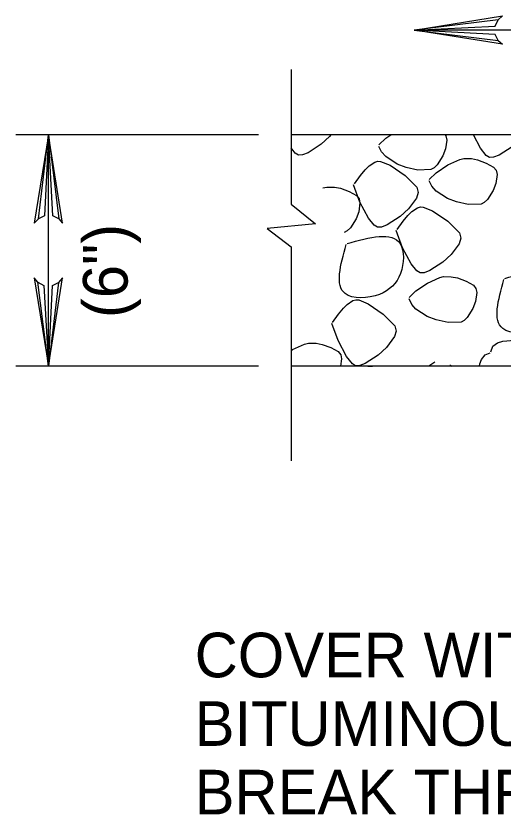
# Model space of a CAD drawing. Extents: x 638455 to 640199, y 298558 to 299152.
# Drawn here: x 639393.4 to 639430.1, y 298625.3 to 298685.5 of the extents above; entities that cross this region are included whole.
import ezdxf

# ---------------------------------------------------------------- set-up
doc = ezdxf.new("R2010")
doc.units = 0
doc.layers.add('2', color=7, linetype='Continuous')
doc.layers.add('3', color=7, linetype='Continuous')

msp = doc.modelspace()

# ---------------------------------------------------------------- linework, layer by layer
at = {"layer": '2'}
for p, q in [((639414.143, 298681.461), (639414.143, 298671.317)), ((639411.704, 298676.533), (639393.444, 298676.533)), ((639395.883, 298659.109), (639395.883, 298676.533)), ((639454.982, 298676.533), (639414.143, 298676.533)), ((639414.143, 298668.094), (639414.143, 298651.994)), ((639411.704, 298659.109), (639393.444, 298659.109)), ((639522.815, 298659.109), (639414.143, 298659.109))]:
    msp.add_line(p, q, dxfattribs=at)
for points in [[(639429.74, 298683.637), (639429.502, 298684.093), (639423.409, 298684.43), (639429.74, 298683.637), (639430.063, 298683.359), (639423.409, 298684.43), (639429.499, 298684.732), (639429.72, 298685.185), (639423.409, 298684.43), (639430.063, 298685.487), (639429.72, 298685.185)], [(639447.803, 298684.43), (639430.379, 298684.43), (639423.409, 298684.43)], [(639396.676, 298670.205), (639396.217, 298670.44), (639395.883, 298676.533), (639396.676, 298670.205), (639396.955, 298669.88), (639395.883, 298676.533), (639395.581, 298670.446), (639395.128, 298670.222), (639395.883, 298676.533), (639394.823, 298669.88), (639395.128, 298670.222)], [(639417.039, 298676.405), (639416.411, 298675.827)], [(639417.134, 298676.533), (639417.039, 298676.405)], [(639421.284, 298676.28), (639421.665, 298676.533)], [(639425.739, 298676.533), (639425.797, 298676.46)], [(639425.797, 298676.46), (639425.858, 298676.146)], [(639428.39, 298675.522), (639427.865, 298676.533)], [(639416.411, 298675.827), (639415.433, 298675.182)], [(639420.759, 298675.778), (639421.284, 298676.28)], [(639425.858, 298676.146), (639425.759, 298675.478)], [(639414.463, 298675.165), (639414.143, 298675.551)], [(639414.71, 298675.017), (639414.463, 298675.165)], [(639415.433, 298675.182), (639415.018, 298675.025)], [(639420.962, 298675.255), (639420.759, 298675.664)], [(639421.276, 298674.895), (639420.962, 298675.255)], [(639425.759, 298675.478), (639425.559, 298674.95)], [(639428.838, 298674.985), (639428.39, 298675.522)], [(639430.786, 298675.647), (639429.805, 298675.002)], [(639415.018, 298675.025), (639414.71, 298675.017)], [(639420.451, 298674.485), (639420.669, 298674.546)], [(639420.669, 298674.546), (639420.881, 298674.537)], [(639420.881, 298674.537), (639421.592, 298674.25)], [(639422.135, 298674.334), (639421.276, 298674.895)], [(639425.559, 298674.95), (639425.138, 298674.27)], [(639425.948, 298674.268), (639426.854, 298674.677)], [(639426.854, 298674.677), (639427.15, 298674.749)], [(639427.15, 298674.749), (639427.731, 298674.744)], [(639427.731, 298674.744), (639428.184, 298674.651)], [(639428.184, 298674.651), (639428.838, 298674.413)], [(639429.082, 298674.837), (639428.838, 298674.985)], [(639429.389, 298674.845), (639429.082, 298674.837)], [(639429.805, 298675.002), (639429.389, 298674.845)], [(639419.731, 298673.913), (639420.018, 298674.198)], [(639420.018, 298674.198), (639420.451, 298674.485)], [(639421.592, 298674.25), (639422.73, 298673.472)], [(639422.803, 298674.079), (639422.135, 298674.334)], [(639423.695, 298673.89), (639422.803, 298674.079)], [(639424.903, 298674.041), (639424.674, 298673.919)], [(639425.138, 298674.27), (639424.903, 298674.041)], [(639425.071, 298673.687), (639425.948, 298674.268)], [(639428.838, 298674.413), (639429.387, 298674.114)], [(639429.387, 298674.114), (639429.584, 298673.867)], [(639418.909, 298672.847), (639419.365, 298673.466)], [(639419.365, 298673.466), (639419.731, 298673.913)], [(639422.73, 298673.472), (639423.61, 298672.595)], [(639424.674, 298673.919), (639423.695, 298673.89)], [(639424.545, 298673.184), (639425.071, 298673.687)], [(639429.645, 298673.556), (639429.546, 298672.885)], [(639429.584, 298673.867), (639429.645, 298673.556)], [(639419.33, 298671.477), (639418.854, 298672.763)], [(639424.749, 298672.662), (639424.545, 298673.071)], [(639429.546, 298672.885), (639429.346, 298672.357)], [(639416.545, 298672.537), (639416.841, 298672.609)], [(639416.841, 298672.609), (639417.422, 298672.604)], [(639417.422, 298672.604), (639417.875, 298672.511)], [(639417.875, 298672.511), (639418.528, 298672.272)], [(639418.528, 298672.272), (639419.078, 298671.973)], [(639423.715, 298672.197), (639423.581, 298671.776)], [(639423.61, 298672.595), (639423.715, 298672.197)], [(639425.062, 298672.301), (639424.749, 298672.662)], [(639425.922, 298671.741), (639425.062, 298672.301)], [(639429.346, 298672.357), (639428.925, 298671.677)], [(639419.078, 298671.973), (639419.275, 298671.727)], [(639419.275, 298671.727), (639419.333, 298671.416)], [(639423.581, 298671.776), (639422.983, 298670.968)], [(639426.59, 298671.485), (639425.922, 298671.741)], [(639428.925, 298671.677), (639428.69, 298671.448)], [(639414.143, 298671.317), (639415.979, 298669.842), (639412.352, 298669.491), (639414.143, 298668.094)], [(639419.333, 298671.416), (639419.237, 298670.745)], [(639419.963, 298670.266), (639419.33, 298671.477)], [(639422.983, 298670.968), (639422.356, 298670.393)], [(639423.227, 298670.759), (639423.663, 298671.05)], [(639423.663, 298671.05), (639423.877, 298671.111)], [(639423.877, 298671.111), (639424.089, 298671.099)], [(639424.089, 298671.099), (639424.801, 298670.815)], [(639427.482, 298671.297), (639426.59, 298671.485)], [(639428.46, 298671.326), (639427.482, 298671.297)], [(639428.69, 298671.448), (639428.46, 298671.326)], [(639419.237, 298670.745), (639419.037, 298670.217)], [(639422.356, 298670.393), (639421.377, 298669.749)], [(639422.574, 298670.03), (639422.942, 298670.475)], [(639422.942, 298670.475), (639423.227, 298670.759)], [(639424.801, 298670.815), (639425.942, 298670.033)], [(639419.037, 298670.217), (639418.616, 298669.537)], [(639420.41, 298669.729), (639419.963, 298670.266)], [(639420.654, 298669.583), (639420.41, 298669.729)], [(639421.377, 298669.749), (639420.962, 298669.589)], [(639422.121, 298669.412), (639422.574, 298670.03)], [(639425.942, 298670.033), (639426.822, 298669.159)], [(639418.38, 298669.307), (639418.148, 298669.186)], [(639418.616, 298669.537), (639418.38, 298669.307)], [(639420.962, 298669.589), (639420.654, 298669.583)], [(639422.542, 298668.041), (639422.062, 298669.328)], [(639426.822, 298669.159), (639426.924, 298668.761)], [(639426.924, 298668.761), (639426.79, 298668.34)], [(639423.175, 298666.83), (639422.542, 298668.041)], [(639426.79, 298668.34), (639426.195, 298667.533)], [(639426.195, 298667.533), (639425.568, 298666.955)], [(639423.619, 298666.293), (639423.175, 298666.83)], [(639425.568, 298666.955), (639424.586, 298666.313)], [(639423.866, 298666.145), (639423.619, 298666.293)], [(639424.171, 298666.154), (639423.866, 298666.145)], [(639424.586, 298666.313), (639424.171, 298666.154)], [(639395.087, 298665.439), (639395.546, 298665.201), (639395.883, 298659.109), (639395.087, 298665.439), (639394.809, 298665.762), (639395.883, 298659.109), (639396.182, 298665.198), (639396.635, 298665.419), (639395.883, 298659.109), (639396.94, 298665.762), (639396.635, 298665.419)], [(639424.424, 298665.378), (639425.332, 298665.788)], [(639425.332, 298665.788), (639425.629, 298665.861)], [(639425.629, 298665.861), (639426.207, 298665.854)], [(639426.207, 298665.854), (639426.663, 298665.762)], [(639426.663, 298665.762), (639427.316, 298665.523)], [(639427.316, 298665.523), (639427.865, 298665.224)], [(639423.547, 298664.797), (639424.424, 298665.378)], [(639427.865, 298665.224), (639428.059, 298664.977)], [(639428.059, 298664.977), (639428.12, 298664.664)], [(639423.024, 298664.295), (639423.547, 298664.797)], [(639428.12, 298664.664), (639428.024, 298663.996)], [(639418.087, 298663.479), (639418.372, 298663.764)], [(639418.372, 298663.764), (639418.804, 298664.054)], [(639418.804, 298664.054), (639419.022, 298664.115)], [(639419.022, 298664.115), (639419.234, 298664.104)], [(639419.234, 298664.104), (639419.946, 298663.819)], [(639419.946, 298663.819), (639421.084, 298663.038)], [(639423.227, 298663.772), (639423.024, 298664.182)], [(639423.538, 298663.412), (639423.227, 298663.772)], [(639428.024, 298663.996), (639427.824, 298663.467)], [(639417.718, 298663.035), (639418.087, 298663.479)], [(639424.397, 298662.852), (639423.538, 298663.412)], [(639427.824, 298663.467), (639427.403, 298662.788)], [(639417.263, 298662.416), (639417.718, 298663.035)], [(639421.084, 298663.038), (639421.964, 298662.161)], [(639425.065, 298662.596), (639424.397, 298662.852)], [(639425.96, 298662.407), (639425.065, 298662.596)], [(639427.168, 298662.558), (639426.935, 298662.436)], [(639427.403, 298662.788), (639427.168, 298662.558)], [(639417.686, 298661.046), (639417.207, 298662.329)], [(639421.964, 298662.161), (639422.068, 298661.766)], [(639426.935, 298662.436), (639425.96, 298662.407)], [(639421.935, 298661.342), (639421.336, 298660.537)], [(639422.068, 298661.766), (639421.935, 298661.342)], [(639414.251, 298660.378), (639415.16, 298660.787)], [(639415.16, 298660.787), (639415.456, 298660.86)], [(639415.456, 298660.86), (639416.037, 298660.854)], [(639416.037, 298660.854), (639416.49, 298660.761)], [(639416.49, 298660.761), (639417.143, 298660.52)], [(639418.316, 298659.835), (639417.686, 298661.046)], [(639429.337, 298660.619), (639429.674, 298660.874)], [(639429.674, 298660.874), (639430.084, 298661.014)], [(639430.084, 298661.014), (639430.961, 298661.08)], [(639414.143, 298660.305), (639414.251, 298660.378)], [(639417.143, 298660.52), (639417.692, 298660.224)], [(639417.692, 298660.224), (639417.89, 298659.977)], [(639421.336, 298660.537), (639420.712, 298659.959)], [(639428.742, 298659.974), (639429.128, 298660.111)], [(639429.183, 298660.195), (639429.337, 298660.619)], [(639417.948, 298659.663), (639417.869, 298659.109)], [(639417.89, 298659.977), (639417.948, 298659.663)], [(639418.764, 298659.297), (639418.316, 298659.835)], [(639420.712, 298659.959), (639419.731, 298659.315)], [(639428.362, 298659.306), (639428.478, 298659.625)], [(639428.478, 298659.625), (639428.742, 298659.974)], [(639419.007, 298659.149), (639418.764, 298659.297)], [(639419.315, 298659.158), (639419.007, 298659.149)], [(639419.731, 298659.315), (639419.315, 298659.158)], [(639419.914, 298659.109), (639419.928, 298659.111)], [(639419.928, 298659.111), (639420.271, 298659.109)], [(639424.479, 298659.109), (639424.525, 298659.155)], [(639424.525, 298659.155), (639424.958, 298659.443)], [(639426.099, 298659.21), (639426.247, 298659.109)], [(639428.329, 298659.109), (639428.362, 298659.306)]]:
    msp.add_lwpolyline(points, dxfattribs=at)
for points in [[(639418.357, 298668.355), (639422.353, 298668.355), (639422.382, 298666.101), (639420.805, 298664.525), (639418.215, 298664.583), (639418.302, 298668.271)], [(639430.226, 298665.721), (639434.225, 298665.721), (639434.251, 298663.47), (639432.677, 298661.893), (639430.086, 298661.949), (639430.171, 298665.637)]]:
    msp.add_spline(points, degree=3, dxfattribs=at)

# ---------------------------------------------------------------- texts
at = {"layer": '3'}
msp.add_text('(6")', height=3.36, rotation=90, dxfattribs=at).set_placement((639401.846, 298662.745))
for s, p in [('COVER WITH 2-PLY', (639406.893, 298635.689)), ('BITUMINOUS PAPER AND', (639406.893, 298630.529)), ('BREAK THROUGH HOLE', (639406.893, 298625.369))]:
    msp.add_text(s, height=3.36, dxfattribs=at).set_placement(p)

doc.saveas('drawing.dxf')
